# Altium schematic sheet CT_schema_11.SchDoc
size 388 x 385 mm
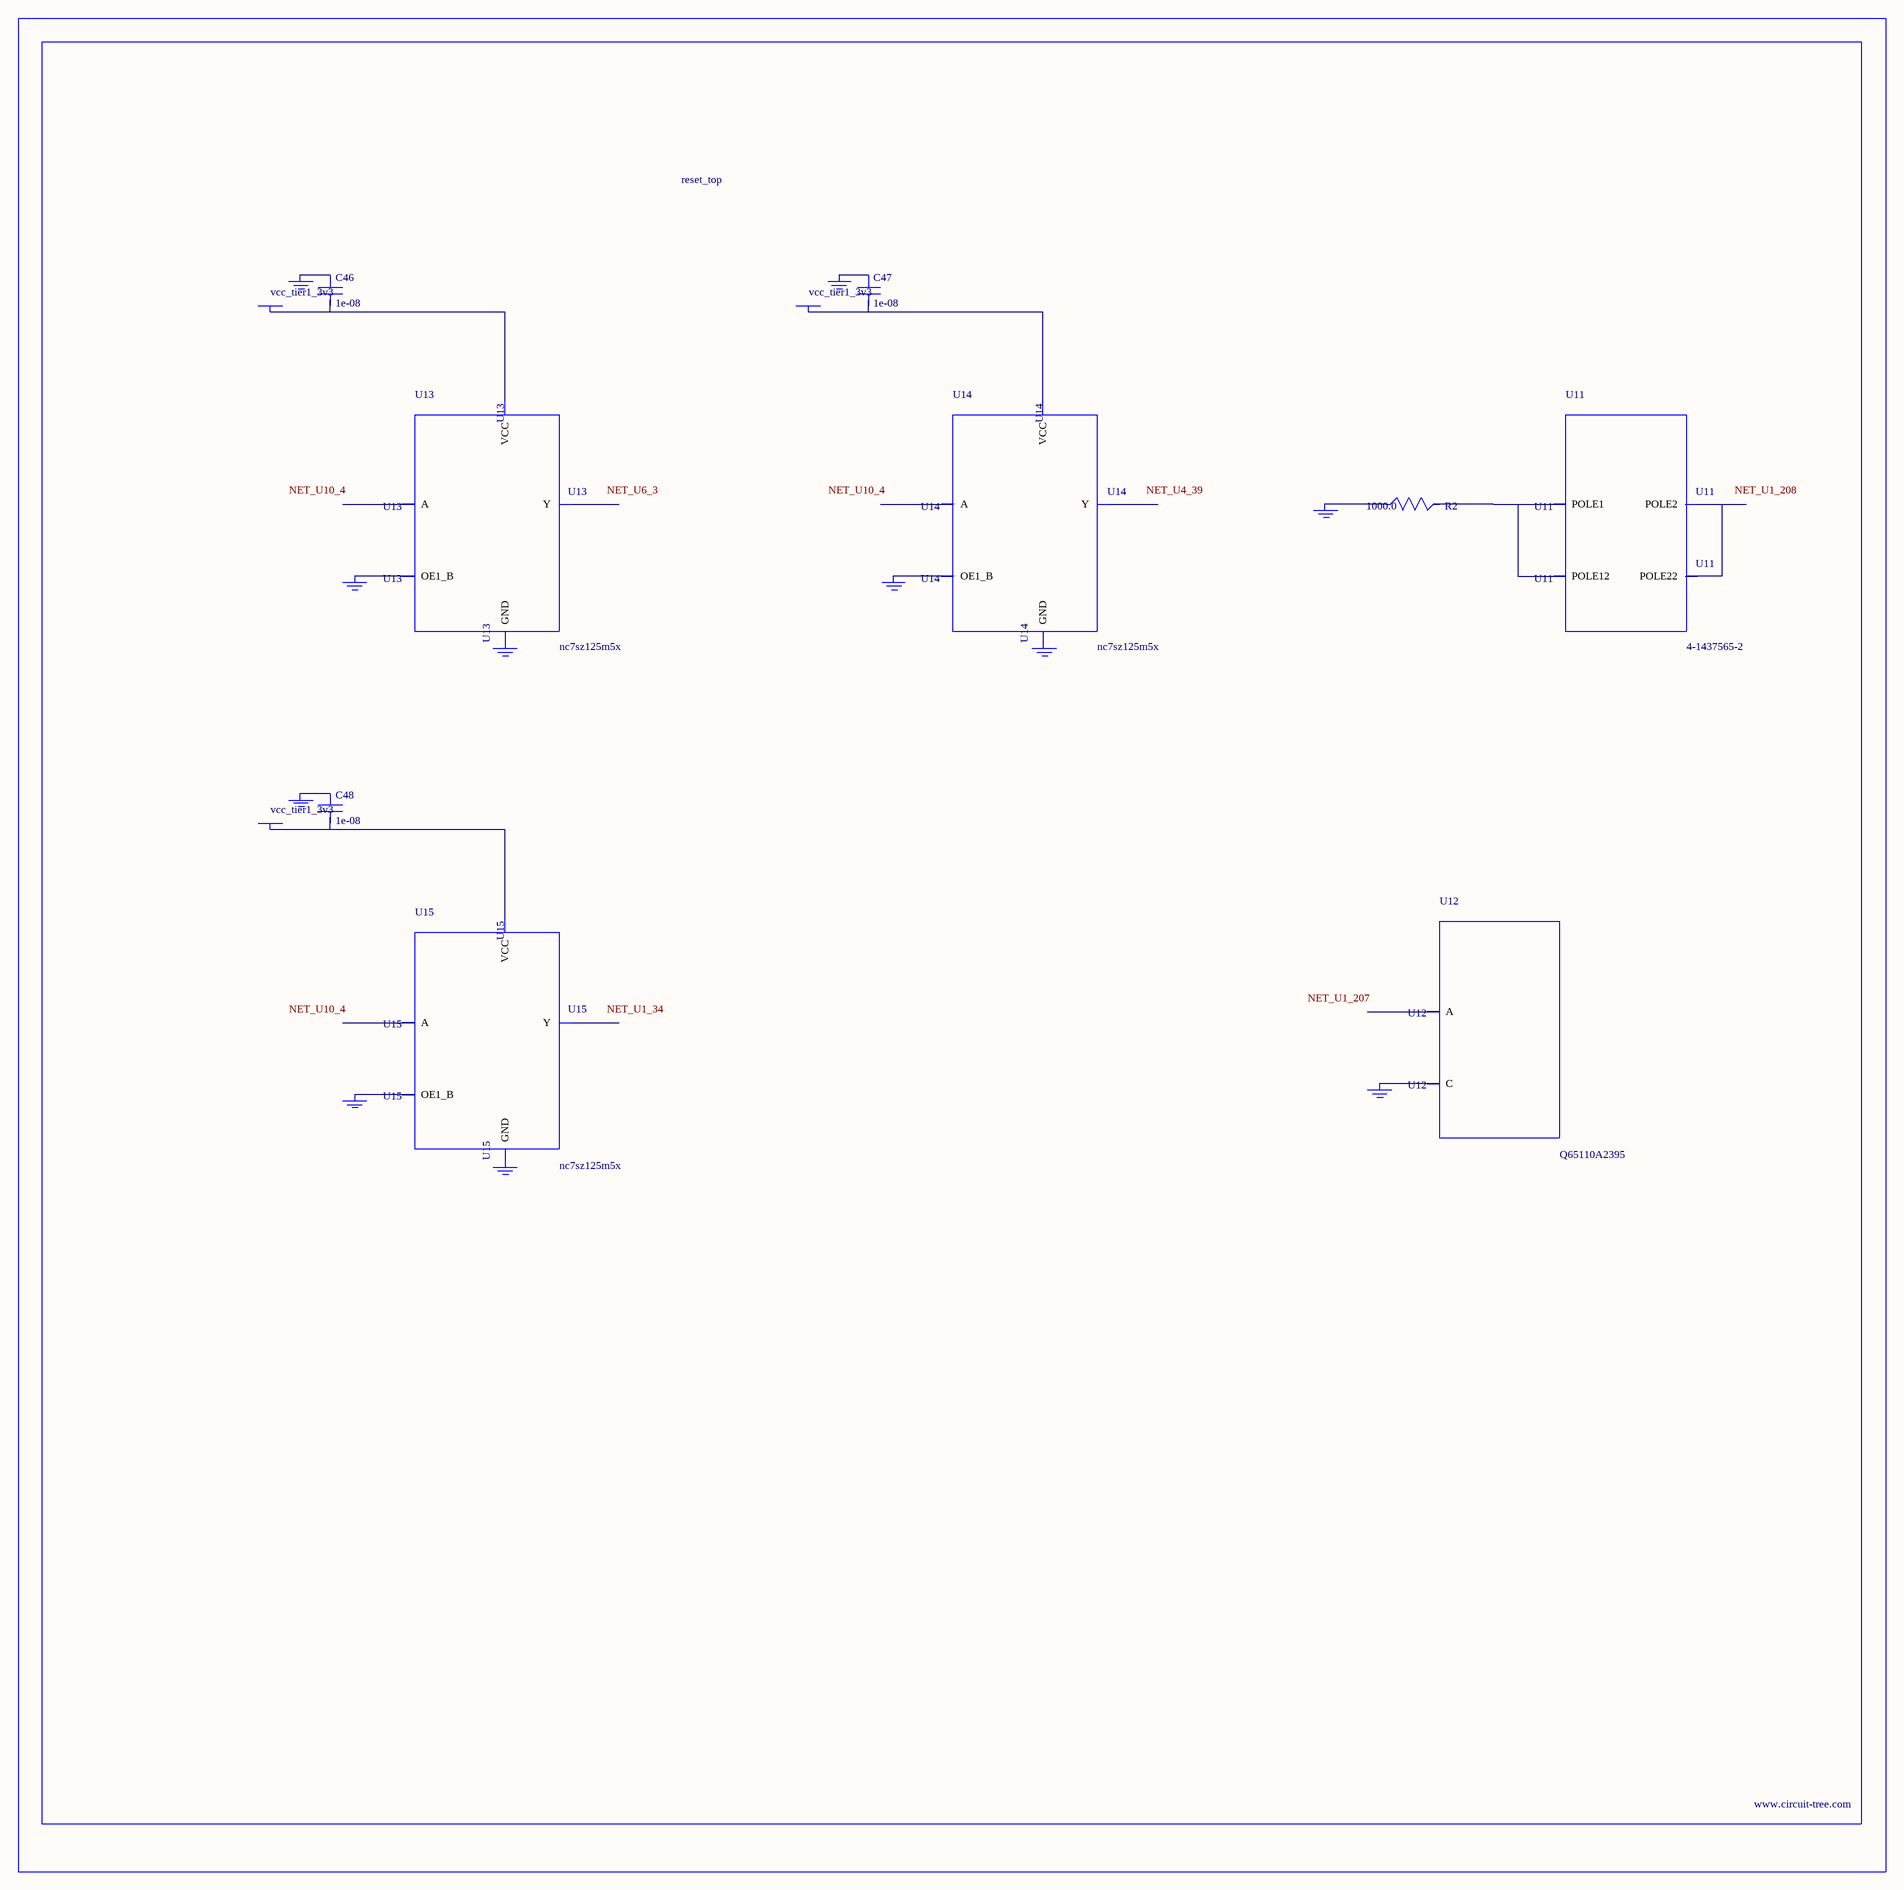
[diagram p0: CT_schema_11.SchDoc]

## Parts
BORDER10  (no value)
C46  1e-08  [C0402]
C47  1e-08  [C0402]
C48  1e-08  [C0402]
GND_INSTANCE_10_0  (no value)
GND_INSTANCE_10_1  (no value)
GND_INSTANCE_10_2  (no value)
GND_INSTANCE_10_3  (no value)
GND_INSTANCE_10_4  (no value)
GND_INSTANCE_10_5  (no value)
GND_INSTANCE_10_6  (no value)
GND_INSTANCE_10_7  (no value)
GND_INSTANCE_10_8  (no value)
GND_INSTANCE_10_9  (no value)
GND_INSTANCE_10_10  (no value)
POWER_INSTANCE_10_0  vcc_tier1_3v3
POWER_INSTANCE_10_1  vcc_tier1_3v3
POWER_INSTANCE_10_2  vcc_tier1_3v3
R2  1000.0  [R0603]
U11  4-1437565-2  [SW_4-1437565-2]
U12  Q65110A2395  [LGM67K-G1J2-24-Z]
U13  nc7sz125m5x  [NC7SZ125M5X]
U14  nc7sz125m5x  [NC7SZ125M5X]
U15  nc7sz125m5x  [NC7SZ125M5X]

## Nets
NetC46_1: C46.1 GND_INSTANCE_10_2.0(GND)
NetC46_2: C46.2 POWER_INSTANCE_10_0.0(PWR) U13.5(VCC)
NetC47_1: C47.1 GND_INSTANCE_10_5.0(GND)
NetC47_2: C47.2 POWER_INSTANCE_10_1.0(PWR) U14.5(VCC)
NetC48_1: C48.1 GND_INSTANCE_10_8.0(GND)
NetC48_2: C48.2 POWER_INSTANCE_10_2.0(PWR) U15.5(VCC)
NetGND_INSTANCE_10_0_0: GND_INSTANCE_10_0.0(GND) R2.1
NetGND_INSTANCE_10_1_0: GND_INSTANCE_10_1.0(GND) U12.C
NetGND_INSTANCE_10_3_0: GND_INSTANCE_10_3.0(GND) U13.1(OE1_B)
NetGND_INSTANCE_10_4_0: GND_INSTANCE_10_4.0(GND) U13.3(GND)
NetGND_INSTANCE_10_6_0: GND_INSTANCE_10_6.0(GND) U14.1(OE1_B)
NetGND_INSTANCE_10_7_0: GND_INSTANCE_10_7.0(GND) U14.3(GND)
NetGND_INSTANCE_10_9_0: GND_INSTANCE_10_9.0(GND) U15.1(OE1_B)
NetGND_INSTANCE_10_10_0: GND_INSTANCE_10_10.0(GND) U15.3(GND)
NetR2_2: R2.2 U11.1(POLE1) U11.2(POLE12)
NetU11_3: U11.3(POLE2) U11.4(POLE22)

Not connected (* = marked no-connect by the designer): U12 A; U13 2(A) 4(Y); U14 2(A) 4(Y); U15 2(A) 4(Y)

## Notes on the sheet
- Labels drawn without touching a wire or pin: NET_U1_34, NET_U1_207, NET_U1_208, NET_U4_39, NET_U6_3, NET_U10_4

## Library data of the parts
BORDER10 = BORDER_PAGE10
C46-C48 = C0402C103K3RAC
GND_INSTANCE_10_0-GND_INSTANCE_10_10 = GND
POWER_INSTANCE_10_0-POWER_INSTANCE_10_2 = PWR
R2 = RC0603JR-071KL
